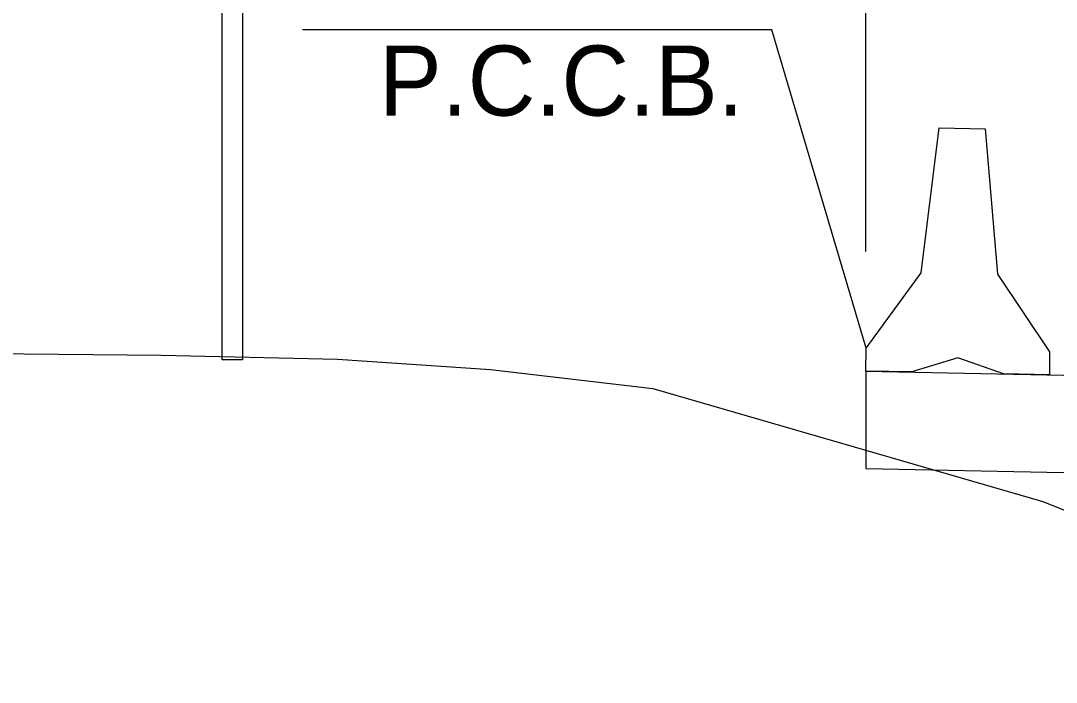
# Model space of a CAD drawing. Extents: x 1807779 to 1818251, y 673292 to 678849.
# Drawn here: x 1813400.8 to 1813507.2, y 678564.5 to 678632.4 of the extents above; entities that cross this region are included whole.
import ezdxf

# ---------------------------------------------------------------- set-up
doc = ezdxf.new("R2010")
doc.units = 0
for name, color, linetype in [('Dimensions', 7, 'Continuous'), ('EX_DRIVEWAY', 7, 'Continuous'), ('Level 1', 7, 'Continuous'), ('T_Drafting', 7, 'Continuous'), ('Vertical Panels', 7, 'Continuous')]:
    doc.layers.add(name, color=color, linetype=linetype)

msp = doc.modelspace()

# ---------------------------------------------------------------- linework, layer by layer
at = {"layer": 'Dimensions'}
for p, q in [((1813487.67, 678608.69), (1813487.67, 678825.67)), ((1813421.53, 678604.08), (1813421.53, 678721.56))]:
    msp.add_line(p, q, dxfattribs=at)
msp.add_lwpolyline([(1813487.69, 678598.77), (1813478, 678631.45), (1813429.78, 678631.45)], dxfattribs=at)
at = {"layer": 'EX_DRIVEWAY'}
for p, q in [((1813487.67, 678596.41), (1813487.67, 678586.41)), ((1813487.67, 678596.41), (1813597.65, 678594.21)), ((1813487.67, 678586.41), (1813700.59, 678582.15))]:
    msp.add_line(p, q, dxfattribs=at)
at = {"layer": 'Level 1'}
for p, q in [((1813493.34, 678606.51), (1813495.21, 678621.4)), ((1813495.21, 678621.4), (1813499.92, 678621.3)), ((1813499.92, 678621.3), (1813501.2, 678606.35)), ((1813487.69, 678598.77), (1813493.34, 678606.51)), ((1813501.2, 678606.35), (1813506.54, 678598.39)), ((1813487.67, 678596.41), (1813487.69, 678598.77)), ((1813506.54, 678598.39), (1813506.52, 678596.03)), ((1813497.12, 678597.79), (1813492.38, 678596.32)), ((1813501.8, 678596.13), (1813497.12, 678597.79)), ((1813492.38, 678596.32), (1813487.67, 678596.41)), ((1813506.52, 678596.03), (1813501.8, 678596.13))]:
    msp.add_line(p, q, dxfattribs=at)
at = {"layer": 'T_Drafting'}
msp.add_lwpolyline([(1812678.82, 678592.81), (1812734.48, 678559.85), (1812877.87, 678504.62), (1812959.16, 678506.76), (1813053.74, 678558.19), (1813144.45, 678595.97), (1813219.03, 678598.12), (1813299.21, 678599.19), (1813415.28, 678598.05), (1813433.38, 678597.64), (1813449.11, 678596.58), (1813465.79, 678594.63), (1813505.84, 678583.03), (1813571.94, 678556.55), (1813690.25, 678508.61), (1813861.67, 678481.8), (1813918.12, 678476.97), (1814104.93, 678475.99), (1814246.73, 678474.07)], dxfattribs=at)
at = {"layer": 'Vertical Panels'}
msp.add_lwpolyline([(1813421.53, 678646.1), (1813423.64, 678646.1), (1813423.64, 678597.56), (1813421.53, 678597.56)], close=True, dxfattribs=at)

# ---------------------------------------------------------------- texts
at = {"layer": 'Dimensions'}
msp.add_text('P.C.C.B.', height=7.2, dxfattribs=at).set_placement((1813437.67, 678622.65))

doc.saveas('drawing.dxf')
